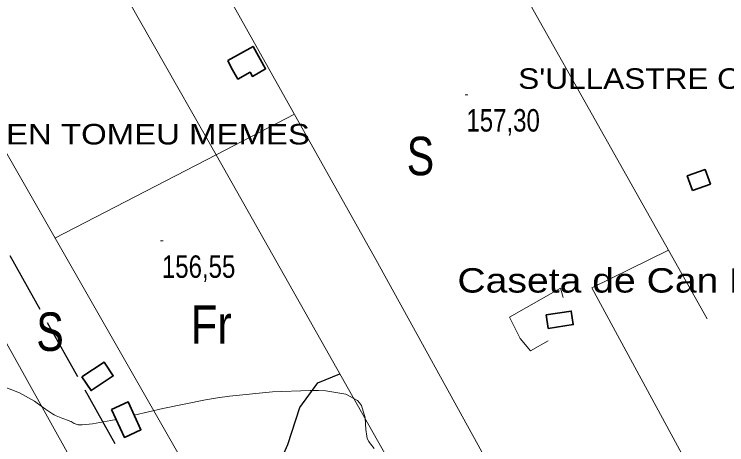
# Model space of a CAD drawing. Extents: x -807245 to 6129983, y -54972206 to 262146364.
# Drawn here: x 489316.8 to 489594.4, y 4382139.7 to 4382307.3 of the extents above; entities that cross this region are included whole.
import ezdxf
from ezdxf.enums import TextEntityAlignment as Align

# ---------------------------------------------------------------- set-up
doc = ezdxf.new("R2010")
doc.units = 0
doc.header["$LTSCALE"] = 4
doc.linetypes.add('LONG_DASHED', pattern=[7.5, 6, -1.5])
for name, color, linetype, lineweight in [('25', 7, 'LONG_DASHED', 25), ('27', 7, 'Continuous', 25), ('39', 7, 'Continuous', 13), ('47', 7, 'Continuous', 35), ('51', 7, 'Continuous', 13), ('7', 7, 'Continuous', 13), ('9', 7, 'Continuous', 13)]:
    doc.layers.add(name, color=color, linetype=linetype, lineweight=lineweight)
doc.layers.add('31', color=7, linetype='Continuous')
doc.layers.add('5', color=7, linetype='Continuous')

msp = doc.modelspace()

# ---------------------------------------------------------------- linework, layer by layer
at = {"layer": '25'}
for points in [[(489271.03, 4382291.96), (489360.67, 4382131.75), (489390.84, 4382082.83), (489403.32, 4382084.98), (489409.62, 4382085.53)], [(489396, 4382109.34), (489408.92, 4382116.9), (489420.27, 4382132.75), (489423.42, 4382139.72), (489427.98, 4382154.15), (489435.04, 4382163.83), (489443.68, 4382167.3)]]:
    msp.add_lwpolyline(points, dxfattribs=at)
at = {"layer": '27'}
msp.add_spline([(491255.21, 4383970.03), (491244.34, 4383967.52), (491230.36, 4383957.66), (491230.81, 4383957.81), (491230.81, 4383957.81), (491220.15, 4383951.47), (491212.7, 4383943.01), (491205.06, 4383944.23), (491184.85, 4383957.71), (491152.82, 4383981.27), (491128.36, 4384004.58), (491128.29, 4384004.88), (491122.26, 4384021.39), (491095.75, 4384034.59), (491071.07, 4384059.32), (491064.71, 4384065.12)], degree=3, dxfattribs=at)
at = {"layer": '39'}
msp.add_spline([(489117.55, 4382698.88), (489119.92, 4382672.68), (489122.01, 4382625.33), (489125.29, 4382585.13), (489126.65, 4382547.13), (489128.77, 4382508.18), (489130.39, 4382475.59), (489130.93, 4382447.55), (489133.21, 4382401.71), (489136.74, 4382363.61), (489144.72, 4382321.33), (489154.17, 4382280.07), (489166.23, 4382246.73), (489180.75, 4382210.53), (489205.22, 4382168.24), (489224.8, 4382133.94), (489257.72, 4382093.12), (489296.35, 4382054.96), (489327.82, 4382028.88), (489364.04, 4382002), (489408.28, 4381978.37), (489453.5, 4381958.06), (489487.73, 4381946.36), (489523.65, 4381936.12), (489563.73, 4381928.23), (489620.66, 4381920.7), (489680.32, 4381912.26), (489735.44, 4381905.59), (489799.91, 4381896.95), (489865.43, 4381887.81), (489926.74, 4381879.18), (489976.6, 4381873.08), (490039.39, 4381865.3), (490107.84, 4381856.38), (490175.25, 4381846.83), (490254.89, 4381836.5), (490348.33, 4381823.47), (490406.14, 4381813.57), (490409.06, 4381812.73)], degree=3, dxfattribs=at)
at = {"layer": '47'}
for points in [[(489400.04, 4382289.35), (489409.82, 4382294.82), (489414.71, 4382286.05), (489409.54, 4382283.16), (489408.64, 4382284.75), (489403.92, 4382282.08), (489401.34, 4382286.63), (489401.25, 4382286.59)], [(489581.07, 4382238.72), (489588.02, 4382241.21), (489585.99, 4382246.86), (489579.04, 4382244.37)], [(489524.87, 4382184.99), (489534.6, 4382186.47), (489533.8, 4382191.71), (489524.07, 4382190.23)], [(489343.12, 4382166.16), (489351.78, 4382171.88), (489355.33, 4382166.5), (489346.67, 4382160.78)], [(489354.64, 4382153.44), (489359.66, 4382142.54), (489366.14, 4382145.52), (489361.12, 4382156.42)]]:
    msp.add_lwpolyline(points, close=True, dxfattribs=at)
at = {"layer": '51'}
for p, q in [((489385.77, 4382049.89), (489254.86, 4382284.84)), ((489395.45, 4382252.58), (489332.63, 4382220.07)), ((489395.45, 4382252.58), (489490.01, 4382085.38))]:
    msp.add_line(p, q, dxfattribs=at)
for points in [[(489547.86, 4382444.72), (489533.51, 4382434.33), (489479.29, 4382406.66), (489451.8, 4382394.89), (489421.77, 4382382.75), (489399.4, 4382373.11), (489375.5, 4382358.34), (489457.61, 4382211.87), (489547.35, 4382049.21), (489584.26, 4381984)], [(489448.87, 4382393.71), (489463.9, 4382366.35), (489475.46, 4382386.41), (489586.82, 4382188.68)], [(489346.31, 4382338.96), (489395.45, 4382252.58), (489425.94, 4382268.38)], [(489287.37, 4382299.16), (489484.32, 4381954.99), (489468.69, 4381959.59), (489464.17, 4381967.37)], [(489571.72, 4382215.49), (489541.78, 4382200.81), (489640.41, 4382019)], [(489530.61, 4382196.97), (489529.63, 4382200.62), (489509.7, 4382189.31), (489513.86, 4382181.08), (489517.94, 4382176.22), (489524.76, 4382180.12)]]:
    msp.add_lwpolyline(points, dxfattribs=at)
at = {"layer": '7'}
for p, q in [((489492.45, 4382276.02), (489493.45, 4382276.02)), ((489373.78, 4382219.04), (489374.78, 4382219.04))]:
    msp.add_line(p, q, dxfattribs=at)
at = {"layer": '9'}
for points in [[(489341.67, 4382147.4), (489340.05, 4382147.9), (489338.87, 4382148.68), (489338.43, 4382148.89), (489337.93, 4382149.1), (489335.71, 4382149.84), (489333.11, 4382150.86), (489332.37, 4382151.25), (489331.63, 4382151.67), (489328.89, 4382153.58), (489325.65, 4382155.89), (489324.59, 4382156.57), (489323.47, 4382157.26), (489318.84, 4382159.93), (489312.78, 4382162.22)], [(489457.07, 4382138.24), (489455.52, 4382140.07), (489455.2, 4382140.5), (489454.92, 4382140.9), (489454.31, 4382142.05), (489453.98, 4382143.87), (489453.89, 4382144.68), (489453.8, 4382145.63), (489453.45, 4382150.18), (489452.09, 4382154.89), (489451.35, 4382155.95), (489450.46, 4382156.9), (489445.95, 4382159.41), (489438.22, 4382160.63), (489435.29, 4382160.77), (489432.03, 4382160.82), (489417.41, 4382160.26), (489400.61, 4382158.57), (489395.97, 4382157.91), (489391.34, 4382157.16), (489374.66, 4382153.74), (489363.54, 4382151.16)], [(489356.43, 4382149.55), (489354.4, 4382149.12), (489347.28, 4382147.78), (489343.24, 4382147.38), (489342.4, 4382147.37), (489341.67, 4382147.4)]]:
    msp.add_lwpolyline(points, dxfattribs=at)

# ---------------------------------------------------------------- texts
at = {"layer": '31'}
for s, width, p in [('S', 0.8, (489475.05, 4382244.63)), ('Fr', 0.85, (489393.52, 4382178.97)), ('S', 0.8, (489330.71, 4382176.2))]:
    msp.add_text(s, height=15, dxfattribs=dict(at, width=width)).set_placement(p, align=Align.CENTER)
at = {"layer": '5'}
for s, height, width, p in [("S'ULLASTRE OLIVERENC", 8, 1.15, (489513.14, 4382278.29)), ("TANCA D'EN TOMEU MEMES", 8, 1.2, (489254.77, 4382256.63)), ('Caseta de Can Montblanc', 9.5, 1.2, (489489.45, 4382198.93))]:
    msp.add_text(s, height=height, dxfattribs=dict(at, width=width)).set_placement(p)
at = {"layer": '7', "width": 0.8}
for s, p in [('157,30', (489492.95, 4382261.65)), ('156,55', (489374.28, 4382204.67))]:
    msp.add_text(s, height=8.75, dxfattribs=at).set_placement(p)

doc.saveas('drawing.dxf')
